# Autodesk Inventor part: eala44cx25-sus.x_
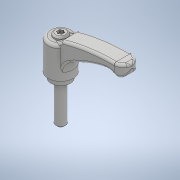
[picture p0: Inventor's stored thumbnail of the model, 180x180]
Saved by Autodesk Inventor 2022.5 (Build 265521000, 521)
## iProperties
Created: 2018-05
Part Number: eala44cx25-sus.x_
Material: 一般
Document SubType Name: Modeling
Designer: imaocorp
Density: 1 g/cm^3
Appearance: 既定
Sending System: SOLIDWORKS 2016-2016286
MC: AMD64
MC_MODEL: AMD64 Family 21 Model 2 Stepping 0, AuthenticAMD
OS: Windows_NT
FRU: Parasolid Version 28.0, build 224,  7-29-2016
FORMAT: text
GUISE: transmit
KEY: eala44cx25-sus
FILE: eala44cx25-sus.x_t
DATE: Fri May 18 11:29:03 2018
Author: imaocorp
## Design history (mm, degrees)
feature "Base1"
node "ソリッド1"
